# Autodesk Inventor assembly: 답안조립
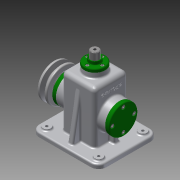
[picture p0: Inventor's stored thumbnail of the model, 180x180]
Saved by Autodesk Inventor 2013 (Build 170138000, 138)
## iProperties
Created: 2016-01
Part Number: 답안조립
Document SubType Name: Assembly
Designer: Administrator
Author: Administrator
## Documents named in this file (19)
- C:\Users\Administrator\Desktop\460127V1002\답안조립.iam
- C:\Users\Administrator\Desktop\460127V1002\1본체.ipt
- C:\Users\Administrator\Desktop\460127V1002\V-벨트풀리.ipt
- C:\Users\Administrator\Desktop\460127V1002\고정핀.ipt
- C:\Users\Administrator\Desktop\460127V1002\뒤커버.ipt
- C:\Users\Administrator\Desktop\460127V1002\링크.ipt
- C:\Users\Administrator\Desktop\460127V1002\멈춤링 6 x 5.ipt
- C:\Users\Administrator\Desktop\460127V1002\멈춤링 15 x 1.ipt
- C:\Users\Administrator\Desktop\460127V1002\베어링 15 x 35 x 11.ipt
- C:\Users\Administrator\Desktop\460127V1002\볼트 M3 x 8.ipt
- C:\Users\Administrator\Desktop\460127V1002\볼트 M4 x 10.ipt
- C:\Users\Administrator\Desktop\460127V1002\볼트 M6 x 12.ipt
- C:\Users\Administrator\Desktop\460127V1002\상부부시.ipt
- C:\Users\Administrator\Desktop\460127V1002\슬라이드바.ipt
- C:\Users\Administrator\Desktop\460127V1002\앞커버.ipt
- C:\Users\Administrator\Desktop\460127V1002\오일실 15 25 7.ipt
- C:\Users\Administrator\Desktop\460127V1002\와셔.ipt
- C:\Users\Administrator\Desktop\460127V1002\키 5 x 5 x 14.ipt
- C:\Users\Administrator\Desktop\460127V1002\편심축.ipt
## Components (16 placed, 6 different names)
1. 1본체:1
2. V-벨트풀리:1 — 각도:2
3. 고정핀:1
4. ISO 4018 M6 x 12:1
5. ISO 4762 M3 x 8:1
6. ISO 4762 M3 x 8:2
7. ISO 4762 M3 x 8:3
8. ISO 4762 M3 x 8:4
9. ISO 4762 M4 x 10:1
10. ISO 4762 M4 x 10:3
11. ISO 4762 M4 x 10:4
12. ISO 4762 M4 x 10:5
13. ISO 4762 M4 x 10:2
14. ISO 4762 M4 x 10:6
15. ISO 4762 M4 x 10:7
16. ISO 4762 M4 x 10:8
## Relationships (1: Angle 1)
- 각도:2 [Angle]: V-벨트풀리:1
